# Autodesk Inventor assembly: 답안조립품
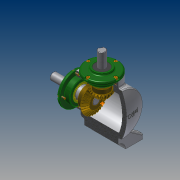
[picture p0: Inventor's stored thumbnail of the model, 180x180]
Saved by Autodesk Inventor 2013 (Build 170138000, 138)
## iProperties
Created: 2017-04
Part Number: 답안조립품
Document SubType Name: Assembly
Designer: Administrator
Author: Administrator
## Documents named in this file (14)
- C:\Users\Administrator\Desktop\470408V1004\답안조립품.iam
- C:\Users\Administrator\Desktop\470408V1004\본체.ipt
- C:\Users\Administrator\Desktop\470408V1004\메인 베벨기어.ipt
- C:\Users\Administrator\Desktop\470408V1004\메인 축.ipt
- 메인 축.ipt
- C:\Users\Administrator\Desktop\470408V1004\베어링 6203.ipt
- C:\Users\Administrator\Desktop\470408V1004\볼트 M4.ipt
- C:\Users\Administrator\Desktop\470408V1004\서브 베벨기어.ipt
- C:\Users\Administrator\Desktop\470408V1004\서브 축.ipt
- 서브 축.ipt
- C:\Users\Administrator\Desktop\470408V1004\오일실 17 32 8.ipt
- C:\Users\Administrator\Desktop\470408V1004\커버.ipt
- C:\Users\Administrator\Desktop\470408V1004\키 4x4.ipt
- C:\Users\Administrator\Desktop\470408V1004\키 5x5.ipt
